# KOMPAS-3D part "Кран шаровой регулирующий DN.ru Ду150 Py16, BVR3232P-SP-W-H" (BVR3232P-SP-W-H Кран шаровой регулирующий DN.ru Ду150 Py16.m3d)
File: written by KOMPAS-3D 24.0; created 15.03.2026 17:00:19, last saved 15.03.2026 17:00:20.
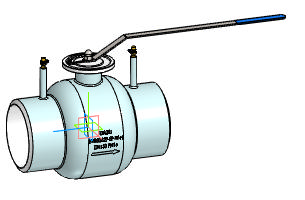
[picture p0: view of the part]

Document properties: Автор: Максим; Полное имя файла: D:\Rabota ebanaya\BVR3232P-SP-W-H Кран шаровой регулирующий Ду15-150\Типоразмеры\DN150\BVR3232P-SP-W-H Кран шаровой регулирующий DN.ru Ду150 Py16.m3d

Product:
- Body: Тело 1  | qty 1
    Масса: 42.097218
- Part/product: Кран шаровой регулирующий DN.ru Ду150 Py16  | designation BVR3232P-SP-W-H
    Масса: 22
    Раздел спецификации: Прочие изделия
    Примечание: D160-69416

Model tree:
1. Операция без истории:1

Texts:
  BVR3232P-SP-W-H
